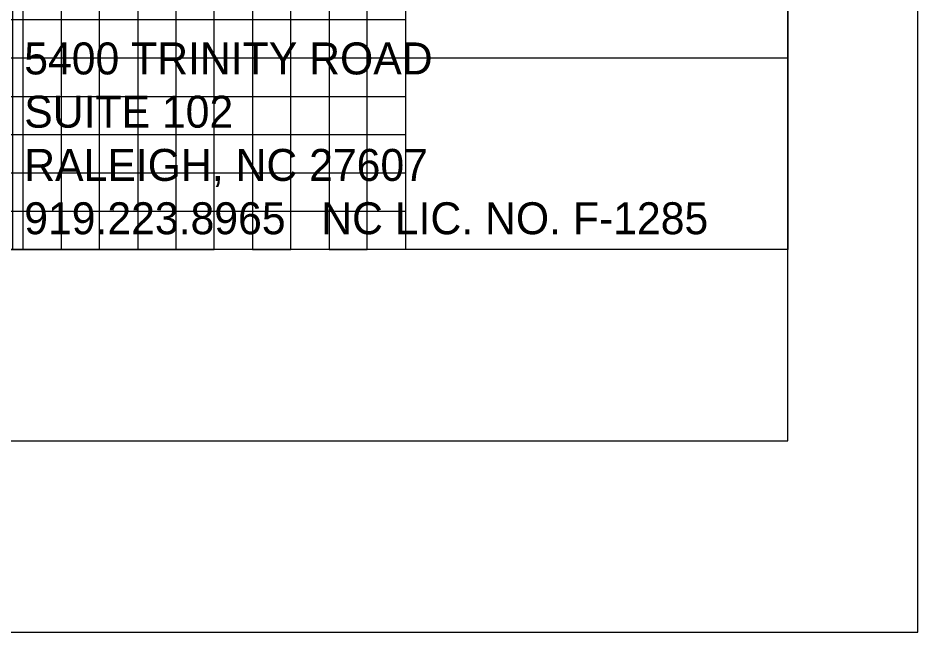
# Model space of a CAD drawing. Extents: x 1524869 to 1526553, y 501099 to 502199.
# Drawn here: x 1526435.4 to 1526553.1, y 501098.6 to 501178.8 of the extents above; entities that cross this region are included whole.
import ezdxf

# ---------------------------------------------------------------- set-up
doc = ezdxf.new("R2010")
doc.units = 0
for name, color, linetype in [('Prop Grid Mask', 7, 'Continuous'), ('Prop Horizontal Alignment Curve and Spiral Data', 7, 'Continuous'), ('Sheet Layout Profile Border Port 2', 7, 'Continuous'), ('Sheet Plot Border Outside CELL', 7, 'Continuous'), ('Sheet Profile CELL', 7, 'Continuous'), ('Sheet Profile Grid Major CELL', 7, 'Continuous'), ('Sheet Profile Grid Middle CELL', 7, 'Continuous'), ('Sheet Profile Grid Minor CELL', 7, 'Continuous')]:
    doc.layers.add(name, color=color, linetype=linetype)

msp = doc.modelspace()

# ---------------------------------------------------------------- linework, layer by layer
at = {"layer": 'Prop Grid Mask'}
msp.add_lwpolyline([(1526434.75, 501200.68), (1526536.08, 501200.68), (1526536.08, 501148.56), (1526434.75, 501148.56)], close=True, dxfattribs=at)
at = {"layer": 'Sheet Layout Profile Border Port 2'}
msp.add_lwpolyline([(1525086.08, 501648.56), (1526486.08, 501648.56), (1526486.08, 501148.56), (1525086.08, 501148.56)], close=True, dxfattribs=at)
at = {"layer": 'Sheet Plot Border Outside CELL'}
msp.add_lwpolyline([(1524869.08, 501098.56), (1526553.08, 501098.56), (1526553.08, 502198.56), (1524869.08, 502198.56)], close=True, dxfattribs=at)
at = {"layer": 'Sheet Profile CELL'}
for p, q in [((1526536.08, 501148.56), (1525036.08, 501148.56)), ((1525036.08, 501123.56), (1526536.08, 501123.56))]:
    msp.add_line(p, q, dxfattribs=at)
msp.add_lwpolyline([(1526536.08, 502173.56), (1525036.08, 502173.56), (1525036.08, 501123.56), (1526536.08, 501123.56)], close=True, dxfattribs=at)
at = {"layer": 'Sheet Profile Grid Major CELL'}
msp.add_line((1526436.08, 501148.56), (1526436.08, 501148.56), dxfattribs=at)
msp.add_line((1526436.08, 501148.56), (1526436.08, 501148.56), dxfattribs=at)
msp.add_line((1526436.08, 501148.56), (1526436.08, 501148.56), dxfattribs=at)
for points in [[(1526086.08, 501148.56), (1526136.08, 501148.56), (1526136.08, 501648.56), (1526186.08, 501648.56), (1526186.08, 501148.56), (1526236.08, 501148.56), (1526236.08, 501648.56), (1526286.08, 501648.56), (1526286.08, 501148.56), (1526336.08, 501148.56), (1526336.08, 501648.56), (1526386.08, 501648.56), (1526386.08, 501148.56), (1526436.08, 501148.56), (1526436.08, 501148.56), (1526436.08, 501648.56), (1526486.08, 501648.56), (1526486.08, 501148.56)], [(1526536.08, 501148.56), (1525036.08, 501148.56)]]:
    msp.add_lwpolyline(points, dxfattribs=at)
at = {"layer": 'Sheet Profile Grid Middle CELL'}
for points in [[(1526111.08, 501148.56), (1526161.08, 501148.56), (1526161.08, 501648.56), (1526211.08, 501648.56), (1526211.08, 501148.56), (1526261.08, 501148.56), (1526261.08, 501648.56), (1526311.08, 501648.56), (1526311.08, 501148.56), (1526361.08, 501148.56), (1526361.08, 501648.56), (1526411.08, 501648.56), (1526411.08, 501148.56), (1526461.08, 501148.56), (1526461.08, 501648.56)], [(1526536.08, 501173.56), (1525036.08, 501173.56)]]:
    msp.add_lwpolyline(points, dxfattribs=at)
at = {"layer": 'Sheet Profile Grid Minor CELL'}
for p, q in [((1526486.08, 501178.56), (1525086.08, 501178.56)), ((1525086.08, 501168.56), (1526486.08, 501168.56)), ((1526486.08, 501163.56), (1525086.08, 501163.56)), ((1525086.08, 501158.56), (1526486.08, 501158.56)), ((1525086.08, 501153.56), (1526486.08, 501153.56)), ((1526486.08, 501153.56), (1526486.08, 501153.56)), ((1526486.08, 501153.56), (1526486.08, 501153.56)), ((1526486.08, 501153.56), (1526486.08, 501153.56))]:
    msp.add_line(p, q, dxfattribs=at)
for points in [[(1526441.08, 501648.56), (1526441.08, 501148.56), (1526446.08, 501148.56), (1526446.08, 501648.56)], [(1526451.08, 501648.56), (1526451.08, 501148.56), (1526456.08, 501148.56), (1526456.08, 501648.56)], [(1526466.08, 501648.56), (1526466.08, 501148.56), (1526471.08, 501148.56), (1526471.08, 501648.56)], [(1526476.08, 501648.56), (1526476.08, 501148.56), (1526481.08, 501148.56), (1526481.08, 501648.56)]]:
    msp.add_lwpolyline(points, dxfattribs=at)

# ---------------------------------------------------------------- texts
at = {"layer": 'Prop Horizontal Alignment Curve and Spiral Data'}
for s, height, p in [('5400 TRINITY ROAD', 4.1773, (1526436.23, 501171.44)), ('SUITE 102', 4.177, (1526436.23, 501164.48)), ('RALEIGH, NC 27607', 4.1773, (1526436.23, 501157.52)), ('919.223.8965   NC LIC. NO. F-1285', 4.1773, (1526436.23, 501150.55))]:
    msp.add_text(s, height=height, rotation=360, dxfattribs=at).set_placement(p)

doc.saveas('drawing.dxf')
